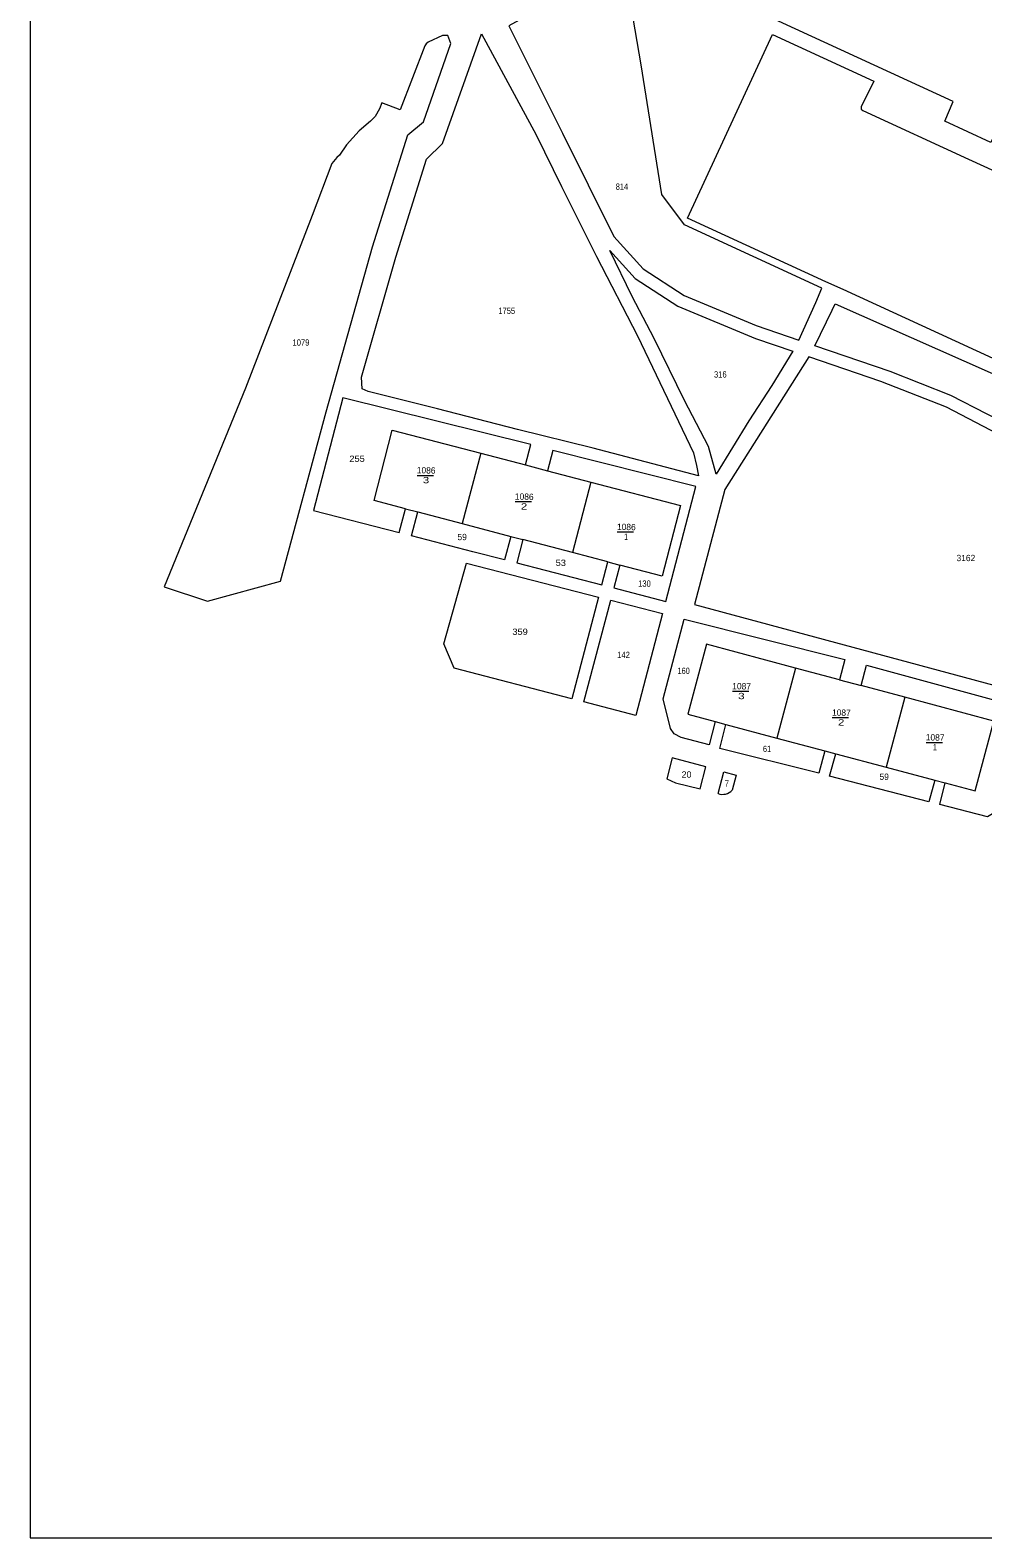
# Model space of a CAD drawing. Extents: x -843400 to -842830, y -1002860 to -1002082.
# Drawn here: x -843400.1 to -843248.8, y -1002860 to -1002620.7 of the extents above; entities that cross this region are included whole.
import ezdxf
from ezdxf.enums import TextEntityAlignment as Align

# ---------------------------------------------------------------- set-up
doc = ezdxf.new("R2010")
doc.units = 0
doc.header["$LTSCALE"] = 0.4
for name, color, linetype, lineweight in [('35', 7, 'Continuous', 13), ('36', 7, 'Continuous', 13), ('38', 7, 'Continuous', 13), ('43', 7, 'Continuous', 13), ('44', 7, 'Continuous', 13)]:
    doc.layers.add(name, color=color, linetype=linetype, lineweight=lineweight)

msp = doc.modelspace()

# ---------------------------------------------------------------- linework, layer by layer
at = {"layer": '35'}
for p, q in [((-843338.632, -1002691.323), (-843336.036, -1002691.323)), ((-843323.053, -1002695.501), (-843320.457, -1002695.501)), ((-843306.84, -1002700.313), (-843304.244, -1002700.313)), ((-843288.531, -1002725.602), (-843285.935, -1002725.602)), ((-843272.689, -1002729.789), (-843270.093, -1002729.789)), ((-843257.797, -1002733.727), (-843255.201, -1002733.727))]:
    msp.add_line(p, q, dxfattribs=at)
at = {"layer": '36'}
msp.add_lwpolyline([(-843234.47, -1002678.6), (-843253.1, -1002670.04), (-843270.96, -1002661.84), (-843273.69, -1002660.61), (-843295.66, -1002650.52), (-843282.21, -1002621.34), (-843266.1, -1002628.73), (-843268.09, -1002632.8), (-843268.1, -1002633.2), (-843267.85, -1002633.42), (-843251.05, -1002641.12), (-843233.78, -1002649.04)], dxfattribs=at)
at = {"layer": '38'}
for p, q in [((-843328.52, -1002687.78), (-843331.46, -1002698.99)), ((-843321.43, -1002689.68), (-843317.92, -1002690.59)), ((-843311.03, -1002692.39), (-843313.97, -1002703.59)), ((-843340.475, -1002696.619), (-843338.541, -1002697.127)), ((-843323.765, -1002701.01), (-843321.831, -1002701.522)), ((-843308.36, -1002705.063), (-843306.426, -1002705.571)), ((-843278.53, -1002721.91), (-843281.5, -1002733.03)), ((-843271.57, -1002723.77), (-843268.12, -1002724.69)), ((-843261.17, -1002726.55), (-843264.13, -1002737.66)), ((-843291.31, -1002730.41), (-843289.6, -1002730.87)), ((-843273.88, -1002735.06), (-843272.15, -1002735.52)), ((-843256.41, -1002739.72), (-843254.75, -1002740.16))]:
    msp.add_line(p, q, dxfattribs=at)
msp.add_lwpolyline([(-843276.99, -1002555.6), (-843271.63, -1002558.06), (-843267.9, -1002550.12), (-843233.22, -1002566.07), (-843229.49, -1002557.91), (-843217.51, -1002563.41), (-843214.18, -1002568.18), (-843216.63, -1002573.61), (-843205.49, -1002578.73), (-843233.93, -1002640.83), (-843246.1, -1002635.37), (-843247.52, -1002638.46), (-843254.81, -1002635.1), (-843253.51, -1002632), (-843281.23, -1002619.2), (-843296.36, -1002612.22), (-843281.484, -1002579.845), (-843280.65, -1002578.03), (-843286.12, -1002575.52)], dxfattribs=at)
at = {"layer": '43'}
msp.add_line((-843287.964, -1002738.899), (-843288.582, -1002741.321), dxfattribs=at)
for points in [[(-843296.15, -1002651.57), (-843299.74, -1002646.72), (-843303.02, -1002626.16), (-843304.63, -1002616.89), (-843306.72, -1002617.26), (-843309.18, -1002617.56), (-843310.69, -1002617.56), (-843313.59, -1002617.01), (-843315.08, -1002616.64), (-843316.08, -1002616.56), (-843317.56, -1002616.79), (-843318.98, -1002617.3), (-843320.76, -1002618.18), (-843324.05, -1002619.99), (-843315.52, -1002637.02), (-843307.41, -1002653.43), (-843302.74, -1002658.55), (-843296.19, -1002662.79), (-843284.8, -1002667.54), (-843278.01, -1002669.84), (-843275.318, -1002663.859), (-843274.325, -1002661.635)], [(-843371.935, -1002711.285), (-843360.309, -1002708.122), (-843353.06, -1002681.26), (-843345.74, -1002655.07), (-843340.13, -1002637.27), (-843337.6, -1002635.22), (-843333.25, -1002622.75), (-843333.73, -1002621.5), (-843334.61, -1002621.49), (-843336.88, -1002622.57), (-843337.2, -1002622.81), (-843337.4, -1002623.12), (-843341.33, -1002633.28), (-843344.21, -1002632.18), (-843344.58, -1002633.15), (-843345.28, -1002634.34), (-843345.92, -1002635), (-843346.06, -1002635.12), (-843347.82, -1002636.65), (-843349.86, -1002638.86), (-843350.98, -1002640.47), (-843351.36, -1002640.87), (-843352.176, -1002641.839), (-843355.31, -1002650.06), (-843365.91, -1002677.51), (-843378.824, -1002709.026)], [(-843328.4, -1002621.24), (-843319.74, -1002637.26), (-843315.71, -1002645.45), (-843310.12, -1002656.56), (-843303.63, -1002669.17), (-843294.741, -1002687.758), (-843294.27, -1002689.76), (-843293.93, -1002691.38), (-843310.66, -1002687.02), (-843322.69, -1002684.06), (-843335.4, -1002680.75), (-843346.41, -1002678.04), (-843347.36, -1002677.58), (-843347.49, -1002675.73), (-843341.99, -1002656.71), (-843337.12, -1002641.14), (-843334.62, -1002638.62)], [(-843308.04, -1002655.61), (-843304.02, -1002660.08), (-843297.21, -1002664.45), (-843284.9, -1002669.59), (-843278.94, -1002671.61), (-843282.31, -1002677.04), (-843285.95, -1002682.68), (-843291.146, -1002691.136), (-843292.37, -1002686.72), (-843296.16, -1002679.46), (-843300.966, -1002669.615), (-843304.49, -1002662.92)], [(-843126.476, -1002752.253), (-843126.528, -1002752.238), (-843154.983, -1002744.549), (-843160.073, -1002741.24), (-843173.21, -1002730.47), (-843184.83, -1002722.53), (-843197.49, -1002714.05), (-843212.96, -1002703.67), (-843228.1, -1002693.51), (-843242.33, -1002684.6), (-843253.86, -1002678.65), (-843263.49, -1002674.86), (-843275.48, -1002670.79), (-843272.718, -1002665.086), (-843272.254, -1002664.121), (-843161.67, -1002713.05), (-843119.43, -1002732.33)], [(-843177.187, -1002730.405), (-843185.333, -1002724.896), (-843198.75, -1002715.9), (-843214.09, -1002705.37), (-843228.82, -1002695.48), (-843242.91, -1002686.57), (-843254.55, -1002680.51), (-843265, -1002676.44), (-843276.39, -1002672.52), (-843289.772, -1002693.597), (-843294.56, -1002711.84), (-843238.17, -1002726.99), (-843231.68, -1002719.95), (-843178.83, -1002736.1), (-843178.26, -1002734.36)], [(-843340.475, -1002696.619), (-843345.45, -1002695.31), (-843342.57, -1002684.16), (-843328.52, -1002687.78), (-843321.43, -1002689.68), (-843320.58, -1002686.44), (-843350.404, -1002679.022), (-843355.085, -1002696.891), (-843341.474, -1002700.417)], [(-843307.381, -1002709.208), (-843299.138, -1002711.329), (-843294.377, -1002693.093), (-843317.08, -1002687.38), (-843317.92, -1002690.59), (-843311.03, -1002692.39), (-843296.79, -1002696.13), (-843299.73, -1002707.33), (-843306.426, -1002705.571)], [(-843331.46, -1002698.99), (-843323.765, -1002701.012), (-843324.752, -1002704.739), (-843329.763, -1002703.45), (-843339.538, -1002700.918), (-843338.541, -1002697.127)], [(-843308.36, -1002705.063), (-843313.97, -1002703.59), (-843321.831, -1002701.522), (-843322.815, -1002705.238), (-843309.318, -1002708.71)], [(-843334.406, -1002718.059), (-843330.771, -1002705.255), (-843309.826, -1002710.645), (-843314.066, -1002726.789), (-843332.77, -1002721.92)], [(-843299.644, -1002713.264), (-843303.868, -1002729.444), (-843312.131, -1002727.293), (-843307.889, -1002711.143)], [(-843271.57, -1002723.77), (-843278.53, -1002721.91), (-843292.66, -1002718.13), (-843295.63, -1002729.26), (-843291.31, -1002730.41), (-843292.26, -1002734.12), (-843296.67, -1002732.96), (-843297.78, -1002732.35), (-843298.38, -1002731.53), (-843299.53, -1002726.78), (-843296.24, -1002714.14), (-843270.71, -1002720.56)], [(-843267.25, -1002721.46), (-843226.684, -1002732.515), (-843228.59, -1002739.56), (-843224.37, -1002740.7), (-843226.15, -1002747.56), (-843243.8, -1002742.97), (-843248.04, -1002745.54), (-843255.63, -1002743.57), (-843254.75, -1002740.16), (-843249.99, -1002741.43), (-843247.03, -1002730.33), (-843261.17, -1002726.55), (-843268.12, -1002724.69)], [(-843281.5, -1002733.03), (-843273.88, -1002735.06), (-843274.82, -1002738.59), (-843290.53, -1002734.67), (-843289.6, -1002730.87)], [(-843297.6, -1002740.16), (-843293.68, -1002741.08), (-843292.79, -1002737.59), (-843298.1, -1002736.15), (-843298.955, -1002739.504)], [(-843264.13, -1002737.66), (-843256.41, -1002739.72), (-843257.35, -1002743.16), (-843273.12, -1002739.08), (-843272.15, -1002735.52)]]:
    msp.add_lwpolyline(points, close=True, dxfattribs=at)
msp.add_lwpolyline([(-843290.837, -1002741.851), (-843289.895, -1002738.375), (-843287.964, -1002738.899)], dxfattribs=at)
msp.add_arc((-843290.1281, -1002739.8046), 2.1657, 250.88941, 315.55292, dxfattribs=at)
at = {"layer": '44'}
msp.add_lwpolyline([(-842830.097, -1002859.997), (-842830.097, -1002081.989), (-843400.094, -1002081.989), (-843400.094, -1002859.997)], close=True, dxfattribs=at)

# ---------------------------------------------------------------- texts
at = {"layer": '35'}
for s, p in [('1086', (-843337.2035, -1002691.0254)), ('1086', (-843321.6235, -1002695.2044)), ('1086', (-843305.4105, -1002700.0154)), ('1087', (-843287.1025, -1002725.3049)), ('1087', (-843271.259, -1002729.4919)), ('1087', (-843256.367, -1002733.4299))]:
    msp.add_text(s, height=1, rotation=358.734, dxfattribs=at).set_placement(p, align=Align.CENTER)
for s, width, p in [('3', 1.4, (-843337.2385, -1002692.5755)), ('2', 1.35, (-843321.658, -1002696.7533)), ('1', 0.7, (-843305.445, -1002701.5649)), ('3', 1.4, (-843287.1365, -1002726.8545)), ('2', 1.35, (-843271.294, -1002731.0413)), ('1', 0.7, (-843256.4025, -1002734.9798))]:
    msp.add_text(s, height=1, rotation=358.734, dxfattribs=dict(at, width=width)).set_placement(p, align=Align.CENTER)
at = {"layer": '43'}
for s, width, p in [('814', 0.85, (-843307.078, -1002645.996)), ('1755', 0.9, (-843325.74, -1002665.701)), ('1079', 0.9, (-843358.418, -1002670.728)), ('316', 0.9, (-843291.477, -1002675.798)), ('255', 1.1, (-843349.398, -1002689.188)), ('53', 1.1, (-843316.631, -1002705.705)), ('130', 0.9, (-843303.525, -1002709.005)), ('359', 1.1, (-843323.506, -1002716.652)), ('142', 0.9, (-843306.844, -1002720.327)), ('160', 0.85, (-843297.28, -1002722.856)), ('61', 0.7, (-843283.705, -1002735.253)), ('20', 1.05, (-843296.621, -1002739.314)), ('7', 0.85, (-843289.765, -1002740.758))]:
    msp.add_text(s, height=1, dxfattribs=dict(at, width=width)).set_placement(p)
for s, p in [('59', (-843332.221, -1002701.612)), ('3162', (-843252.957, -1002704.945)), ('59', (-843265.189, -1002739.669))]:
    msp.add_text(s, height=1, dxfattribs=at).set_placement(p)

doc.saveas('drawing.dxf')
